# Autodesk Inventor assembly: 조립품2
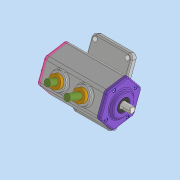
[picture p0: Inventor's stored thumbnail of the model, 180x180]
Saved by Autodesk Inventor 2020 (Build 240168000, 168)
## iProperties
Created: 2021-06
Part Number: 조립품2
Document SubType Name: Assembly
Designer: MIRAE
Author: MIRAE
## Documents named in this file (11)
- C:\Users\MIRAE\Desktop\710606V1016\답안조립품.iam
- C:\Users\MIRAE\Desktop\710606V1016\본체.ipt
- C:\Users\MIRAE\Desktop\710606V1016\슬라이더.ipt
- C:\Users\MIRAE\Desktop\710606V1016\베어링 6302.ipt
- C:\Users\MIRAE\Desktop\710606V1016\편심축.ipt
- C:\Users\MIRAE\Desktop\710606V1016\앞커버.ipt
- C:\Users\MIRAE\Desktop\710606V1016\뒷커버.ipt
- C:\Users\MIRAE\Desktop\710606V1016\베어링 6203.ipt
- C:\Users\MIRAE\Desktop\710606V1016\부시.ipt
- C:\Users\MIRAE\Desktop\710606V1016\오일실.ipt
- C:\Users\MIRAE\Desktop\710606V1016\볼트 M4.ipt
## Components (10 placed, 3 different names)
1. 7-베어링 6203:1
2. 8-오일실:1
3. 9-M4-소켓머리:2
4. 9-M4-소켓머리:3
5. 9-M4-소켓머리:4
6. 9-M4-소켓머리:5
7. 9-M4-소켓머리:6
8. 9-M4-소켓머리:7
9. 9-M4-소켓머리:8
10. 9-M4-소켓머리:9
